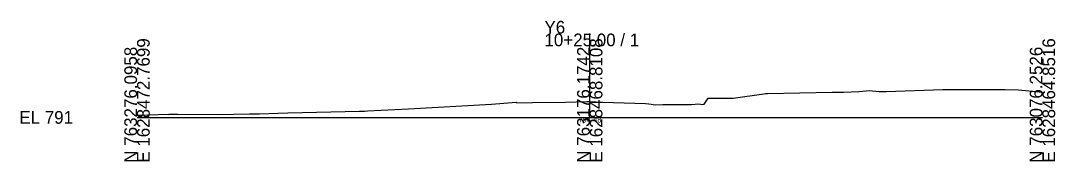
# Model space of a CAD drawing. Extents: x -26 to 203, y -10 to 6017.
# Drawn here: x -25.7 to 202.8, y 490.3 to 521.4 of the extents above; entities that cross this region are included whole.
import ezdxf

# ---------------------------------------------------------------- set-up
doc = ezdxf.new("R2010")
doc.units = 0
for name, color, linetype in [('Default', 7, 'Continuous'), ('Exist Cross Section Cell', 7, 'Continuous'), ('Exist XS Center Line Elevation Label', 7, 'Continuous'), ('Exist XS Ground Line', 7, 'Continuous')]:
    doc.layers.add(name, color=color, linetype=linetype)

msp = doc.modelspace()

# ---------------------------------------------------------------- linework, layer by layer
at = {"layer": 'Exist Cross Section Cell'}
for p, q in [((100, 500), (100, 518.52)), ((0, 500), (100, 500)), ((100, 500), (200, 500))]:
    msp.add_line(p, q, dxfattribs=at)
at = {"layer": 'Exist XS Ground Line'}
msp.add_lwpolyline([(0, 500.51), (7.05, 500.71), (9, 500.72), (17.95, 500.63), (24.87, 500.76), (27.08, 500.78), (31.13, 500.97), (33.3, 501), (49.12, 501.38), (50.25, 501.4), (50.92, 501.45), (59.97, 501.93), (78.33, 502.96), (83.75, 503.38), (83.88, 503.23), (87.33, 503.29), (94.65, 503.4), (99.36, 503.51), (100, 503.48), (102.89, 503.37), (112.32, 503.04), (113.06, 502.99), (114.53, 502.81), (116.13, 502.86), (122.49, 502.88), (124.11, 502.97), (124.85, 502.88), (125.3, 502.93), (126.16, 504.23), (131.17, 504.22), (131.65, 504.26), (138.44, 505.21), (138.82, 505.26), (139.27, 505.27), (153.52, 505.6), (156.09, 505.58), (159.46, 505.69), (161.03, 505.89), (161.69, 505.94), (163.93, 505.73), (165.53, 505.72), (177.98, 506.14), (191.8, 506.17), (194.71, 506.12), (200, 505.59)], dxfattribs=at)

# ---------------------------------------------------------------- texts
at = {"layer": 'Default'}
msp.add_text('-', height=0.0001, dxfattribs=at).set_placement((0, 500))
at = {"layer": 'Exist Cross Section Cell'}
for s, p in [('Y6', (90, 518.52)), ('10+25.00 / 1', (90, 515.72)), ('EL 791', (-26, 498.6))]:
    msp.add_text(s, height=2.8, dxfattribs=at).set_placement(p)
for s, p in [('E 1628472.7699', (2.8, 490)), ('E 1628468.8108', (102.8, 490)), ('E 1628464.8516', (202.8, 490)), ('N 763276.0958', (0, 490)), ('N 763176.1742', (100, 490)), ('N 763076.2526', (200, 490))]:
    msp.add_text(s, height=2.8, rotation=90, dxfattribs=at).set_placement(p)
at = {"layer": 'Exist XS Center Line Elevation Label'}
msp.add_text('794.48', height=1.2, dxfattribs=at).set_placement((97.52, 498.88))

doc.saveas('drawing.dxf')
